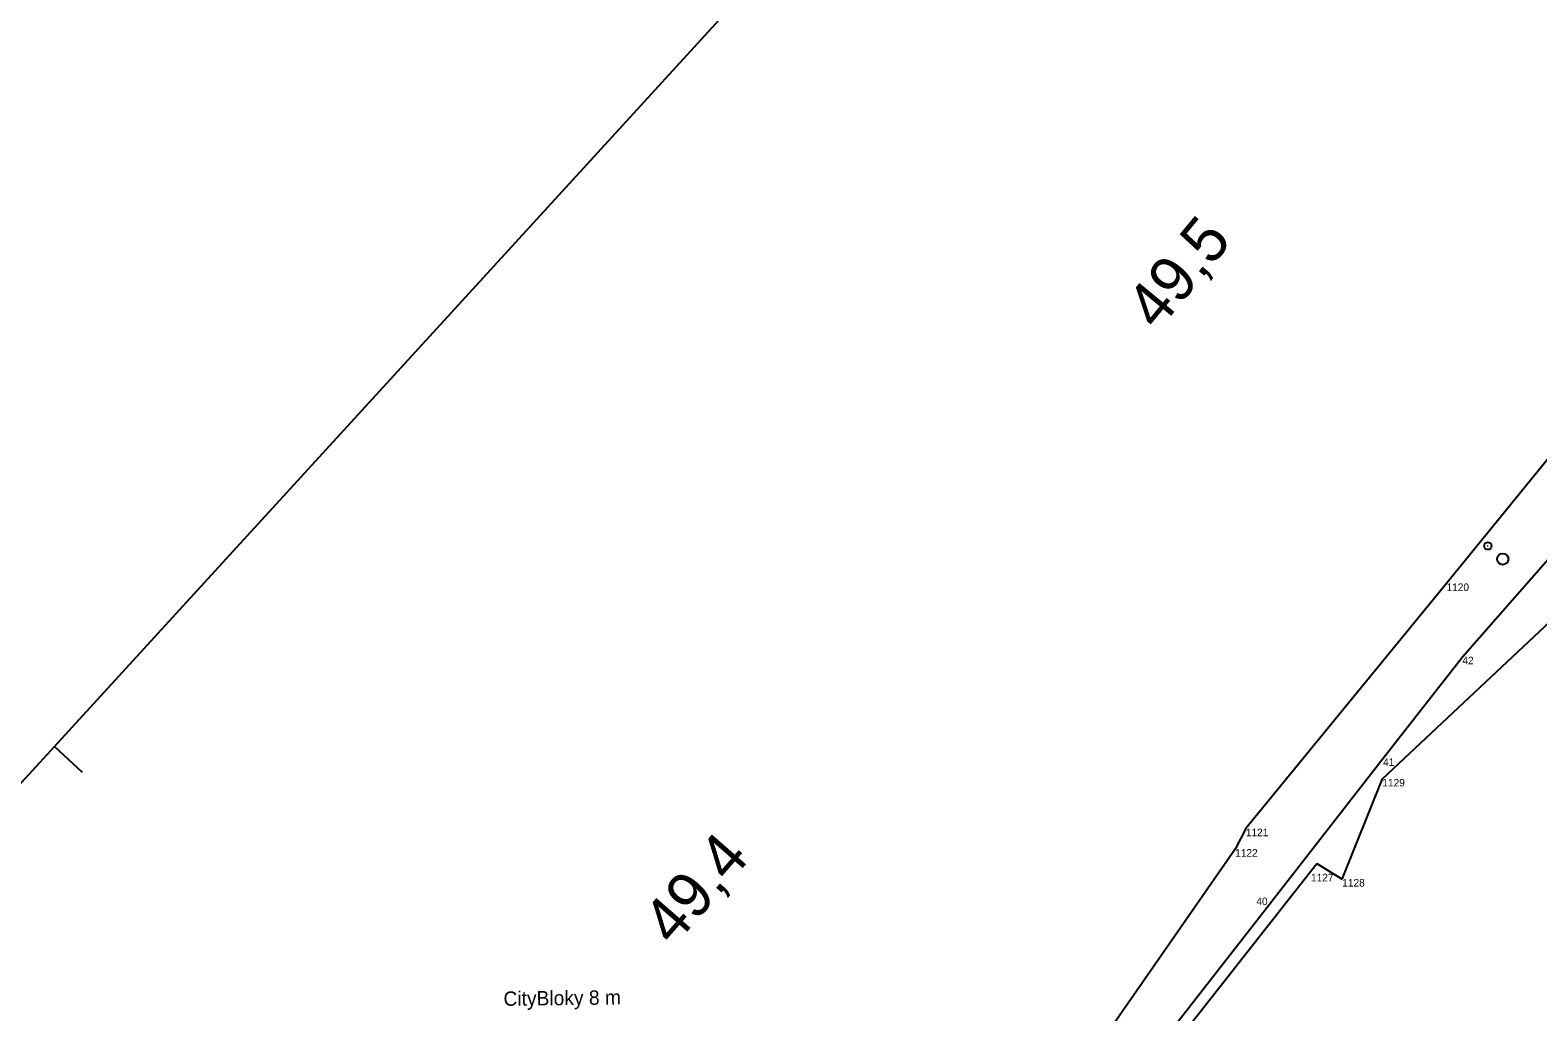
# Model space of a CAD drawing. Extents: x -678683 to -677755, y -1006946 to -1005971.
# Drawn here: x -678402.7 to -678203.3, y -1006471 to -1006341.2 of the extents above; entities that cross this region are included whole.
import ezdxf

# ---------------------------------------------------------------- set-up
doc = ezdxf.new("R2010")
doc.units = 0
for name, color, linetype in [('rozpiska - Lichá Tisk', 7, 'Continuous'), ('SSZT nové - lomové body', 7, 'Continuous'), ('SSZT_nové', 7, 'Continuous'), ('SŽDC', 7, 'Continuous'), ('SŽDC - body', 7, 'Continuous'), ('Vrstva 7', 7, 'Continuous')]:
    doc.layers.add(name, color=color, linetype=linetype)

msp = doc.modelspace()

# ---------------------------------------------------------------- linework, layer by layer
at = {"layer": 'rozpiska - Lichá Tisk'}
for p, q in [((-678399.5, -1006435.89), (-678257.76, -1006280.94)), ((-678541.24, -1006590.84), (-678399.5, -1006435.89)), ((-678399.5, -1006435.89), (-678395.81, -1006439.27))]:
    msp.add_line(p, q, dxfattribs=at)
at = {"layer": 'SSZT nové - lomové body'}
for p, q in [((-678213.31, -1006424.02), (-678213.31, -1006424.02)), ((-678223.79, -1006437.46), (-678223.79, -1006437.46)), ((-678238.83, -1006456.75), (-678238.83, -1006456.75))]:
    msp.add_line(p, q, dxfattribs=at)
at = {"layer": 'SSZT_nové'}
msp.add_lwpolyline([(-678276.52, -1006503.93), (-678257.42, -1006480.58), (-678238.83, -1006456.75), (-678223.79, -1006437.46), (-678213.31, -1006424.02), (-678199.43, -1006408.27)], dxfattribs=at)
at = {"layer": 'SŽDC'}
for p, q in [((-678194.69, -1006388.87), (-678215.4, -1006414.33)), ((-678223.89, -1006440.18), (-678187.52, -1006406.01)), ((-678215.4, -1006414.33), (-678241.94, -1006446.76)), ((-678229.19, -1006453.42), (-678223.89, -1006440.18)), ((-678241.94, -1006446.76), (-678243.35, -1006449.47)), ((-678243.35, -1006449.47), (-678259.32, -1006472.44)), ((-678265.21, -1006492.84), (-678232.55, -1006451.35)), ((-678232.55, -1006451.35), (-678229.19, -1006453.42))]:
    msp.add_line(p, q, dxfattribs=at)
at = {"layer": 'SŽDC - body'}
for p, q in [((-678215.4, -1006414.33), (-678215.4, -1006414.33)), ((-678223.89, -1006440.18), (-678223.89, -1006440.18)), ((-678241.94, -1006446.76), (-678241.94, -1006446.76)), ((-678243.35, -1006449.47), (-678243.35, -1006449.47)), ((-678232.55, -1006451.35), (-678232.55, -1006451.35)), ((-678229.19, -1006453.42), (-678229.19, -1006453.42))]:
    msp.add_line(p, q, dxfattribs=at)
at = {"layer": 'Vrstva 7'}
msp.add_line((-678209.97, -1006409.4), (-678209.91, -1006409.32), dxfattribs=at)
for centre, radius in [((-678209.94, -1006409.36), 0.5), ((-678207.97, -1006411.1), 0.75)]:
    msp.add_circle(centre, radius, dxfattribs=at)

# ---------------------------------------------------------------- texts
at = {"layer": 'SSZT nové - lomové body'}
for s, p in [('42', (-678213.31, -1006425.02)), ('41', (-678223.79, -1006438.46)), ('40', (-678240.55, -1006456.87))]:
    msp.add_text(s, height=1, dxfattribs=at).set_placement(p)
at = {"layer": 'SSZT_nové'}
msp.add_text('CityBloky 8 m', height=1.9, rotation=0.7098, dxfattribs=at).set_placement((-678340.1, -1006470.2))
at = {"layer": 'SŽDC - body'}
for s, p in [('1120', (-678215.4, -1006415.33)), ('1129', (-678223.89, -1006441.18)), ('1121', (-678241.94, -1006447.76)), ('1122', (-678243.35, -1006450.47)), ('1127', (-678233.32, -1006453.73)), ('1128', (-678229.19, -1006454.42))]:
    msp.add_text(s, height=1, dxfattribs=at).set_placement(p)
at = {"layer": 'Vrstva 7'}
for s, rotation, p in [('49,5', 50.4282, (-678253.59, -1006381.08)), ('49,4', 48.8843, (-678317.64, -1006462.48))]:
    msp.add_text(s, height=6, rotation=rotation, dxfattribs=at).set_placement(p)

doc.saveas('drawing.dxf')
